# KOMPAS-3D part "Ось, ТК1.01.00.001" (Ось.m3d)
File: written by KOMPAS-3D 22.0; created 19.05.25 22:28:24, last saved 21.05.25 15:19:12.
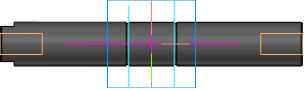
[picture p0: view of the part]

Document properties: Автор: user; Полное имя файла: ТК1.01.00.001 - Ось.cdw

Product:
- Body: Тело 8
    Материал: Сталь 40Х ГОСТ 4543-2016 (density 7850 kg/m3)
- Part/product: Ось  | designation ТК1.01.00.001
    Материал: Сталь 40Х ГОСТ 4543-2016 (density 7850 kg/m3)
    Масса: 0.62382
    Форматы листов документа: A4

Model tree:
1. Эскиз:1
2. Эскиз:2
3. Элемент выдавливания:1
     Расстояние 1 = 172
4. Линейный размер:1  (with: Элемент выдавливания:1)
     Значение = 172
5. Отверстие:1  (with: Элемент выдавливания:1)  (labels: M12)
     Глубина выреза = 26; Диаметр отверстия = 10.1056; Угол конуса дна = 118
6. M12  (with: Элемент выдавливания:1)  (labels: cil0_24705-2004 coarse)
     Длина резьбы = 24; Шаг резьбы = 1.75; Номинальный диаметр резьбы = 12
7. Зеркальный массив:1
8. Экземпляр ( 1 )
9. Экземпляр ( 2 )  (with: Отверстие:1)
10. Эскиз:3  (with: Элемент выдавливания:1, Отверстие:1)
11. Элемент выдавливания:2
     Расстояние 2 = 8
12. Зеркальный массив:2  (with: Экземпляр ( 1 ), Экземпляр ( 2 ), Элемент выдавливания:2)
13. Смещенная плоскость:1
     Расстояние = 12.9
14. Смещенная плоскость:2
     Расстояние = 12.9
15. Ось конической поверхности:11  (with: Элемент выдавливания:1)
16. Смещенная плоскость:19  (with: Элемент выдавливания:1)
17. ЛСК:11  (with: Плоскость XY, Плоскость ZX, Плоскость ZY, Ось X, Ось Y, Ось Z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)
     Ось X. X = -1; Ось Y. Y = -1; Ось Z. Z = 1; Точка начала. Х = -86
18. Эскиз:12
19. Присоединительная точка:5
     Перенос X = -72.4; Расстояние = -72.4
20. Элемент вращения:5
     Угол 1 = 360
21. Канавка наружная 25 ГОСТ 13944-86
22. Зеркальный массив:3  (with: Экземпляр ( 1 ), Экземпляр ( 2 ), Элемент вращения:5)
23. Фаска:1  (with: Элемент выдавливания:1)  (labels: Сталь 40Х ГОСТ 4543-2016; BOSimple***Material:5b3b2396-5625-11d7-8827-00508b01a93a)
     Угол = 45; Длина 1 = 1; Длина 2 = 1

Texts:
  KTE.LIST=eu.7SspS.gtzAFSo09OUaa
  Edge1
  Edge2
  Справочник стандартных изделий
  ТК1.01.00.001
